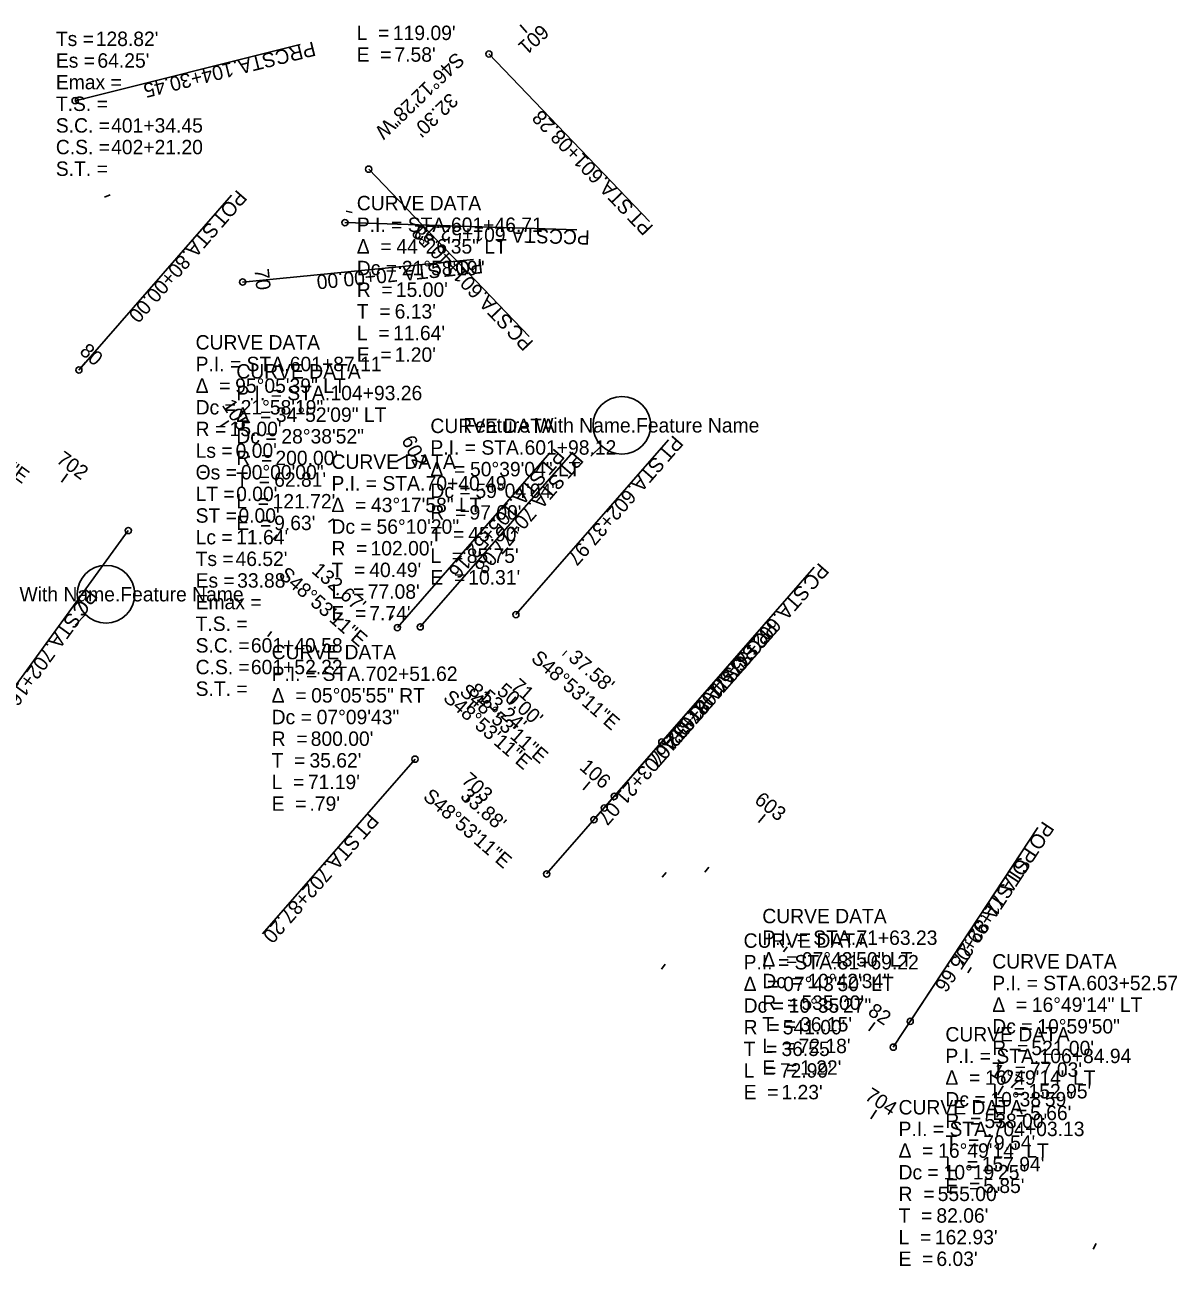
# Model space of a CAD drawing. Extents: x 1600023 to 1602131, y 285824 to 287284.
# Drawn here: x 1601004.6 to 1601228.2, y 286445.4 to 286686.3 of the extents above; entities that cross this region are included whole.
import ezdxf

# ---------------------------------------------------------------- set-up
doc = ezdxf.new("R2010")
doc.units = 0
for name, color, linetype in [('_CIVIL_CONSTRUCTION', 7, 'Continuous'), ('Default', 7, 'Continuous'), ('GE_P_Alignment', 7, 'Continuous'), ('PF_P_Grade_Line', 7, 'Continuous'), ('PF_X_Ground_Line', 7, 'Continuous'), ('PV_P_Curb', 7, 'Continuous'), ('SC_Scratch6', 7, 'Continuous'), ('SC_Scratch8', 7, 'Continuous')]:
    doc.layers.add(name, color=color, linetype=linetype)

msp = doc.modelspace()

# ---------------------------------------------------------------- linework, layer by layer
at = {"layer": '_CIVIL_CONSTRUCTION'}
for p, q in [((1601014.4, 286671.56), (1601058.06, 286682.46)), ((1601076.94, 286569.32), (1601106.53, 286603.23)), ((1601117.05, 286534.32), (1601146.64, 286568.22))]:
    msp.add_line(p, q, dxfattribs=at)
for centre in [(1601014.4, 286671.56), (1601076.94, 286569.32), (1601117.05, 286534.32)]:
    msp.add_circle(centre, 0.6, dxfattribs=at)
at = {"layer": 'Default'}
for p, q in [((1601100.72, 286686.28), (1601102.07, 286684.8)), ((1601094.67, 286680.62), (1601125.81, 286648.14)), ((1601071.36, 286658.27), (1601102.5, 286625.79)), ((1601015.12, 286619.3), (1601044.71, 286653.2)), ((1601066.98, 286650.11), (1601068.16, 286649.89)), ((1601066.74, 286647.9), (1601111.72, 286646.52)), ((1601046.9, 286636.37), (1601091.69, 286640.76)), ((1601046.9, 286636.37), (1601048.89, 286636.57)), ((1601015.12, 286619.3), (1601016.43, 286620.8)), ((1601099.91, 286571.84), (1601129.5, 286605.74)), ((1601081.35, 286569.46), (1601110.94, 286603.36)), ((1601076.86, 286601.7), (1601078.65, 286602.59)), ((1601011.75, 286597.56), (1601012.93, 286599.18)), ((1601063.53, 286589.75), (1601064.53, 286590.42)), ((1601024.7, 286588.15), (1600998.24, 286551.75)), ((1601052.79, 286586.42), (1601053.58, 286587.32)), ((1601128.23, 286547.13), (1601157.81, 286581.03)), ((1601119.02, 286536.58), (1601148.61, 286570.48)), ((1601051.76, 286567.59), (1601052.51, 286568.53)), ((1601108.98, 286563.92), (1601109.77, 286564.83)), ((1601115.07, 286532.06), (1601144.66, 286565.96)), ((1601090.46, 286553.54), (1601091.77, 286555.05)), ((1601098.61, 286554.39), (1601099.93, 286555.89)), ((1601105.87, 286521.51), (1601135.46, 286555.41)), ((1601080.34, 286543.79), (1601050.75, 286509.88)), ((1601089.99, 286535.37), (1601091.31, 286536.88)), ((1601147.02, 286531.48), (1601148.26, 286533.05)), ((1601176.43, 286492.92), (1601201.2, 286530.5)), ((1601173.13, 286487.91), (1601197.89, 286525.49)), ((1601128.31, 286520.88), (1601129.07, 286521.8)), ((1601136.6, 286521.88), (1601137.35, 286522.82)), ((1601128.15, 286503.07), (1601128.89, 286504.01)), ((1601187.62, 286502.34), (1601188.27, 286503.34)), ((1601168.42, 286491.05), (1601169.54, 286492.71)), ((1601168.82, 286474.01), (1601169.9, 286475.69)), ((1601211.93, 286448.73), (1601212.49, 286449.79))]:
    msp.add_line(p, q, dxfattribs=at)
for centre in [(1601094.67, 286680.62), (1601071.36, 286658.27), (1601066.74, 286647.9), (1601046.9, 286636.37), (1601015.12, 286619.3), (1601024.7, 286588.15), (1601099.91, 286571.84), (1601081.35, 286569.46), (1601128.23, 286547.13), (1601080.34, 286543.79), (1601119.02, 286536.58), (1601115.07, 286532.06), (1601105.87, 286521.51), (1601176.43, 286492.92), (1601173.13, 286487.91)]:
    msp.add_circle(centre, 0.6, dxfattribs=at)
at = {"layer": 'PV_P_Curb'}
for centre in [(1601120.48, 286608.57), (1601020.39, 286575.8)]:
    msp.add_circle(centre, 5.6, dxfattribs=at)
at = {"layer": 'SC_Scratch6'}
for p, q in [((1601020.06, 286652.85), (1601021.19, 286653.26)), ((1601042.53, 286608.33), (1601044.19, 286609.45)), ((1601075.32, 286570.76), (1601076.12, 286571.65)), ((1601112.98, 286537.87), (1601114.29, 286539.38)), ((1601151.83, 286506.42), (1601152.54, 286507.38)), ((1601193.41, 286478.68), (1601194.44, 286480.4))]:
    msp.add_line(p, q, dxfattribs=at)
at = {"layer": 'SC_Scratch8'}
for p, q in [((1601114.48, 286602.57), (1601116.52, 286604.61)), ((1601014.39, 286569.8), (1601016.43, 286571.84))]:
    msp.add_line(p, q, dxfattribs=at)
for points in [[(1601114.48, 286602.57), (1601115.19, 286603.28), (1601115.19, 286603.28)], [(1601014.39, 286569.8), (1601015.1, 286570.5), (1601015.1, 286570.5)]]:
    msp.add_lwpolyline(points, close=True, dxfattribs=at)

# ---------------------------------------------------------------- texts
at = {"layer": '_CIVIL_CONSTRUCTION'}
for s, rotation, p in [('PRC', 194.0171, (1601060.62, 286683.06)), (' STA. ', 194.0171, (1601053.89, 286681.38)), ('104+30.45', 194.0171, (1601044.72, 286679.09)), ('PT', 228.8864, (1601107.49, 286604.27)), (' STA. ', 228.8864, (1601104.59, 286600.94)), ('105+52.16', 228.8864, (1601098.37, 286593.82)), ('PC', 228.8864, (1601147.65, 286569.32)), (' STA. ', 228.8864, (1601144.63, 286565.86)), ('106+05.40', 228.8864, (1601138.42, 286558.74))]:
    msp.add_text(s, height=2.8, rotation=rotation, dxfattribs=at).set_placement(p)
at = {"layer": 'Default'}
for s, p in [("128.82'", (1601018.39, 286682.16)), ('Ts = ', (1601010.65, 286682.16)), ('Es = ', (1601010.65, 286677.96)), ("64.25'", (1601018.72, 286677.96)), ('Emax = ', (1601010.65, 286673.76)), ('T.S. = ', (1601010.65, 286669.56)), ('S.C. = ', (1601010.65, 286665.36)), ('401+34.45', (1601021.38, 286665.36)), ('C.S. = ', (1601010.65, 286661.16)), ('402+21.20', (1601021.38, 286661.16)), ('S.T. = ', (1601010.65, 286656.96)), ('CURVE DATA', (1601069.05, 286650.29)), ('P.I. = STA. ', (1601069.05, 286646.09)), ('601+46.71', (1601087.32, 286646.09)), ('Δ  = ', (1601069.05, 286641.89)), ('44°26\'35" LT', (1601076.73, 286641.89)), ('Dc = ', (1601069.05, 286637.69)), ('21°58\'19"', (1601077.79, 286637.69)), ('R  = ', (1601069.05, 286633.49)), ("15.00'", (1601076.63, 286633.49)), ('T  = ', (1601069.05, 286629.29)), ("6.13'", (1601076.39, 286629.29)), ('L  = ', (1601069.05, 286625.09)), ("11.64'", (1601076.09, 286625.09)), ('CURVE DATA', (1601037.77, 286623.27)), ('E  = ', (1601069.05, 286620.89)), ("1.20'", (1601076.39, 286620.89)), ('P.I. = STA. ', (1601037.77, 286619.07)), ('601+87.11', (1601056.04, 286619.07)), ('Δ  = ', (1601037.77, 286614.87)), ('95°05\'39" LT', (1601045.45, 286614.87)), ('Dc = ', (1601037.77, 286610.67)), ('21°58\'19"', (1601046.51, 286610.67)), ('R = ', (1601037.77, 286606.47)), ("15.00'", (1601044.36, 286606.47)), ('CURVE DATA', (1601083.33, 286607.07)), ('P.I. = STA. ', (1601083.33, 286602.87)), ('601+98.12', (1601101.6, 286602.87)), ('Ls = ', (1601037.77, 286602.27)), ("0.00'", (1601045.53, 286602.27)), ('Θs = ', (1601037.77, 286598.07)), ('00°00\'00"', (1601046.57, 286598.07)), ('CURVE DATA', (1601064.13, 286600.12)), ('Δ  = ', (1601083.33, 286598.67)), ('50°39\'04" LT', (1601091.01, 286598.67)), ('P.I. = STA. ', (1601064.13, 286595.92)), ('70+40.49', (1601082.39, 286595.92)), ('LT = ', (1601037.77, 286593.87)), ("0.00'", (1601045.63, 286593.87)), ('Dc = ', (1601083.33, 286594.47)), ('59°04\'04"', (1601092.07, 286594.47)), ('Δ  = ', (1601064.13, 286591.72)), ('43°17\'58" LT', (1601071.8, 286591.72)), ('ST = ', (1601037.77, 286589.67)), ("0.00'", (1601046.08, 286589.67)), ('R  = ', (1601083.33, 286590.27)), ("97.00'", (1601090.91, 286590.27)), ('Dc = ', (1601064.13, 286587.52)), ('56°10\'20"', (1601072.87, 286587.52)), ('T  = ', (1601083.33, 286586.07)), ("45.90'", (1601090.67, 286586.07)), ('Lc = ', (1601037.77, 286585.47)), ("11.64'", (1601045.65, 286585.47)), ('Ts = ', (1601037.77, 286581.27)), ("46.52'", (1601045.51, 286581.27)), ('R  = ', (1601064.13, 286583.32)), ("102.00'", (1601071.71, 286583.32)), ('L  = ', (1601083.33, 286581.87)), ("85.75'", (1601090.37, 286581.87)), ('T  = ', (1601064.13, 286579.12)), ("40.49'", (1601071.46, 286579.12)), ('Es = ', (1601037.77, 286577.07)), ("33.88'", (1601045.83, 286577.07)), ('E  = ', (1601083.33, 286577.67)), ("10.31'", (1601090.67, 286577.67)), ('L  = ', (1601064.13, 286574.92)), ("77.08'", (1601071.17, 286574.92)), ('Emax = ', (1601037.77, 286572.87)), ('E  = ', (1601064.13, 286570.72)), ("7.74'", (1601071.47, 286570.72)), ('T.S. = ', (1601037.77, 286568.67)), ('S.C. = ', (1601037.77, 286564.47)), ('601+40.58', (1601048.49, 286564.47)), ('CURVE DATA', (1601052.52, 286563.17)), ('C.S. = ', (1601037.77, 286560.27)), ('601+52.22', (1601048.49, 286560.27)), ('P.I. = STA. ', (1601052.52, 286558.97)), ('702+51.62', (1601070.79, 286558.97)), ('S.T. = ', (1601037.77, 286556.07)), ('Δ  = ', (1601052.52, 286554.77)), ('05°05\'55" RT', (1601060.2, 286554.77)), ('Dc = ', (1601052.52, 286550.57)), ('07°09\'43"', (1601061.26, 286550.57)), ('R  = ', (1601052.52, 286546.37)), ("800.00'", (1601060.1, 286546.37)), ('T  = ', (1601052.52, 286542.17)), ("35.62'", (1601059.86, 286542.17)), ('L  = ', (1601052.52, 286537.97)), ("71.19'", (1601059.56, 286537.97)), ('E  = ', (1601052.52, 286533.77)), (".79'", (1601059.86, 286533.77)), ('CURVE DATA', (1601147.73, 286511.95)), ('CURVE DATA', (1601144.1, 286507.19)), ('P.I. = STA. ', (1601147.73, 286507.75)), ('71+63.23', (1601165.99, 286507.75)), ('P.I. = STA. ', (1601144.1, 286502.99)), ('Δ  = ', (1601147.73, 286503.55)), ('07°43\'50" LT', (1601155.4, 286503.55)), ('81+69.22', (1601162.37, 286502.99)), ('CURVE DATA', (1601192.35, 286503.16)), ('Dc = ', (1601147.73, 286499.35)), ('10°42\'34"', (1601156.47, 286499.35)), ('Δ  = ', (1601144.1, 286498.79)), ('07°43\'50" LT', (1601151.78, 286498.79)), ('P.I. = STA. ', (1601192.35, 286498.96)), ('603+52.57', (1601210.61, 286498.96)), ('Dc = ', (1601144.1, 286494.59)), ('R  = ', (1601147.73, 286495.15)), ('10°35\'27"', (1601152.84, 286494.59)), ("535.00'", (1601155.31, 286495.15)), ('Δ  = ', (1601192.35, 286494.76)), ('16°49\'14" LT', (1601200.02, 286494.76)), ('R  = ', (1601144.1, 286490.39)), ('T  = ', (1601147.73, 286490.95)), ("541.00'", (1601151.69, 286490.39)), ("36.15'", (1601155.06, 286490.95)), ('Dc = ', (1601192.35, 286490.56)), ('10°59\'50"', (1601201.09, 286490.56)), ('T  = ', (1601144.1, 286486.19)), ('L  = ', (1601147.73, 286486.75)), ("36.55'", (1601151.44, 286486.19)), ("72.18'", (1601154.77, 286486.75)), ('R  = ', (1601192.35, 286486.36)), ("521.00'", (1601199.93, 286486.36)), ('E  = ', (1601147.73, 286482.55)), ("1.22'", (1601155.07, 286482.55)), ('L  = ', (1601144.1, 286481.99)), ("72.99'", (1601151.14, 286481.99)), ('T  = ', (1601192.35, 286482.16)), ("77.03'", (1601199.68, 286482.16)), ('E  = ', (1601144.1, 286477.79)), ("1.23'", (1601151.44, 286477.79)), ('L  = ', (1601192.35, 286477.96)), ("152.95'", (1601199.39, 286477.96)), ('CURVE DATA', (1601174.17, 286474.85)), ('E  = ', (1601192.35, 286473.76)), ("5.66'", (1601199.69, 286473.76)), ('P.I. = STA. ', (1601174.17, 286470.65)), ('704+03.13', (1601192.44, 286470.65)), ('Δ  = ', (1601174.17, 286466.45)), ('16°49\'14" LT', (1601181.85, 286466.45)), ('Dc = ', (1601174.17, 286462.25)), ('10°19\'25"', (1601182.91, 286462.25)), ('R  = ', (1601174.17, 286458.05)), ("555.00'", (1601181.76, 286458.05)), ('T  = ', (1601174.17, 286453.85)), ("82.06'", (1601181.51, 286453.85)), ('L  = ', (1601174.17, 286449.65)), ("162.93'", (1601181.22, 286449.65)), ('E  = ', (1601174.17, 286445.45)), ("6.03'", (1601181.51, 286445.45))]:
    msp.add_text(s, height=2.8, dxfattribs=at).set_placement(p)
for s, rotation, p in [('601', 222.3413, (1601104.73, 286686.55)), ('S46°12\'28"W', 223.7922, (1601088.28, 286681.14)), ("32.30'", 223.7922, (1601087.06, 286673.26)), ('601+08.28', 133.7922, (1601117.15, 286657.11)), (' STA. ', 133.7922, (1601123.69, 286650.29)), ('POT', 228.8864, (1601045.85, 286654.44)), ('PT', 133.7922, (1601126.75, 286647.1)), (' STA. ', 228.8864, (1601041.11, 286649.01)), ('601+40.58', 133.7922, (1601093.78, 286634.82)), ('601+52.22', 178.2352, (1601097.96, 286646.9)), (' STA. ', 178.2352, (1601107.41, 286646.61)), ('PCC', 178.2352, (1601114.3, 286646.4)), ('80+00.00', 228.8864, (1601034.9, 286641.89)), (' STA. ', 185.587, (1601086.2, 286640.18)), ('POT', 185.587, (1601093.37, 286640.88)), ('70', 275.587, (1601049.18, 286638.84)), ('70+00.00', 185.587, (1601076.79, 286639.26)), (' STA. ', 133.7922, (1601100.32, 286628)), ('PC', 133.7922, (1601103.49, 286624.69)), ('80', 318.8864, (1601015.08, 286622.65)), ('S53°59\'06"E', 323.985, (1600987.16, 286609.5)), ('602', 296.4597, (1601077.64, 286605.75)), ('PT', 228.8864, (1601130.51, 286606.82)), ('702', 323.985, (1601010.57, 286601.51)), ('PT', 228.8864, (1601111.15, 286603.54)), (' STA. ', 228.8864, (1601127.6, 286603.5)), (' STA. ', 228.8864, (1601108.25, 286600.22)), ('602+37.97', 228.8864, (1601121.39, 286596.38)), ('70+77.08', 228.8864, (1601102.03, 286593.09)), ("132.67'", 318.8864, (1601060.09, 286580.1)), ('PC', 228.8864, (1601158.78, 286582.07)), ('S48°53\'11"E', 318.8864, (1601053.7, 286579.25)), ('PC', 233.985, (1601016.67, 286577.04)), (' STA. ', 228.8864, (1601155.76, 286578.62)), (' STA. ', 233.985, (1601013.98, 286573.33)), ('602+75.54', 228.8864, (1601149.55, 286571.49)), ('PC', 228.8864, (1601148.88, 286570.73)), ('702+16.01', 233.985, (1601008.42, 286565.69)), ('S48°53\'11"E', 318.8864, (1601102.67, 286563.06)), ("37.58'", 318.8864, (1601109.91, 286563.17)), (' STA. ', 228.8864, (1601145.86, 286567.27)), ('PC', 228.8864, (1601144.99, 286566.27)), (' STA. ', 228.8864, (1601141.97, 286562.81)), ('S48°53\'11"E', 318.8864, (1601088.79, 286556.59)), ('81', 318.8864, (1601090.57, 286556.76)), ("50.00'", 318.8864, (1601096.02, 286556.71)), ('71', 318.8864, (1601098.73, 286557.61)), ('71+27.08', 228.8864, (1601139.65, 286560.15)), ('81+32.67', 228.8864, (1601135.76, 286555.69)), ('PC', 228.8864, (1601136.52, 286556.56)), (' STA. ', 228.8864, (1601133.5, 286553.11)), ('703+21.07', 228.8864, (1601127.29, 286545.99)), ('703', 318.8864, (1601089.17, 286539.4)), ('S48°53\'11"E', 318.8864, (1601081.71, 286536.23)), ("33.88'", 318.8864, (1601088.94, 286536.34)), ('603', 321.5759, (1601146.01, 286535.48)), ('PT', 228.8864, (1601071.44, 286533.52)), ('POT', 236.6168, (1601202.19, 286531.94)), (' STA. ', 228.8864, (1601068.53, 286530.19)), ('POT', 236.6168, (1601198.86, 286526.88)), (' STA. ', 236.6168, (1601198.23, 286525.92)), ('702+87.20', 228.8864, (1601062.32, 286523.07)), (' STA. ', 236.6168, (1601194.9, 286520.87)), ('71+99.27', 236.6168, (1601193.03, 286518.03)), ('82+05.66', 236.6168, (1601189.7, 286512.97)), ('82', 326.017, (1601168.02, 286494.34)), ('704', 327.0343, (1601167.43, 286477.89))]:
    msp.add_text(s, height=2.8, rotation=rotation, dxfattribs=at).set_placement(p)
at = {"layer": 'GE_P_Alignment'}
msp.add_text('S48°53\'11"E', height=2.8, rotation=318.8864, dxfattribs=at).set_placement((1601085.6, 286555.4))
at = {"layer": 'PF_P_Grade_Line'}
msp.add_text("53.24'", height=2.8, rotation=318.8864, dxfattribs=at).set_placement((1601092.83, 286555.51))
at = {"layer": 'PF_X_Ground_Line'}
for s, p in [('L  = ', (1601069.01, 286683.32)), ("119.09'", (1601076.05, 286683.32)), ('E  = ', (1601069.01, 286679.12)), ("7.58'", (1601076.35, 286679.12)), ('CURVE DATA', (1601045.67, 286617.64)), ('P.I. = STA. ', (1601045.67, 286613.44)), ('104+93.26', (1601063.94, 286613.44)), ('Δ  = ', (1601045.67, 286609.24)), ('34°52\'09" LT', (1601053.35, 286609.24)), ('Dc = ', (1601045.67, 286605.04)), ('28°38\'52"', (1601054.41, 286605.04)), ('R  = ', (1601045.67, 286600.84)), ("200.00'", (1601053.25, 286600.84)), ('T  = ', (1601045.67, 286596.64)), ("62.81'", (1601053.01, 286596.64)), ('L  = ', (1601045.67, 286592.44)), ("121.72'", (1601052.71, 286592.44)), ('E  = ', (1601045.67, 286588.24)), ("9.63'", (1601053.01, 286588.24)), ('CURVE DATA', (1601183.26, 286489.01)), ('P.I. = STA. ', (1601183.26, 286484.81)), ('106+84.94', (1601201.53, 286484.81)), ('Δ  = ', (1601183.26, 286480.61)), ('16°49\'14" LT', (1601190.94, 286480.61)), ('Dc = ', (1601183.26, 286476.41)), ('10°38\'59"', (1601192, 286476.41)), ('R  = ', (1601183.26, 286472.21)), ("538.00'", (1601190.84, 286472.21)), ('T  = ', (1601183.26, 286468.01)), ("79.54'", (1601190.6, 286468.01)), ('L  = ', (1601183.26, 286463.81)), ("157.94'", (1601190.3, 286463.81)), ('E  = ', (1601183.26, 286459.61)), ("5.85'", (1601190.6, 286459.61))]:
    msp.add_text(s, height=2.8, dxfattribs=at).set_placement(p)
at = {"layer": 'PV_P_Curb'}
for p in [(1601089.73, 286607.17), (1600989.65, 286574.4)]:
    msp.add_text('Feature With Name.Feature Name', height=2.8, dxfattribs=at).set_placement(p)
at = {"layer": 'SC_Scratch6'}
for s, rotation, p in [('105', 303.9428, (1601042.76, 286612.47)), ('106', 318.8864, (1601112.09, 286541.96)), ('107', 328.9612, (1601191.77, 286482.59))]:
    msp.add_text(s, height=2.8, rotation=rotation, dxfattribs=at).set_placement(p)

doc.saveas('drawing.dxf')
